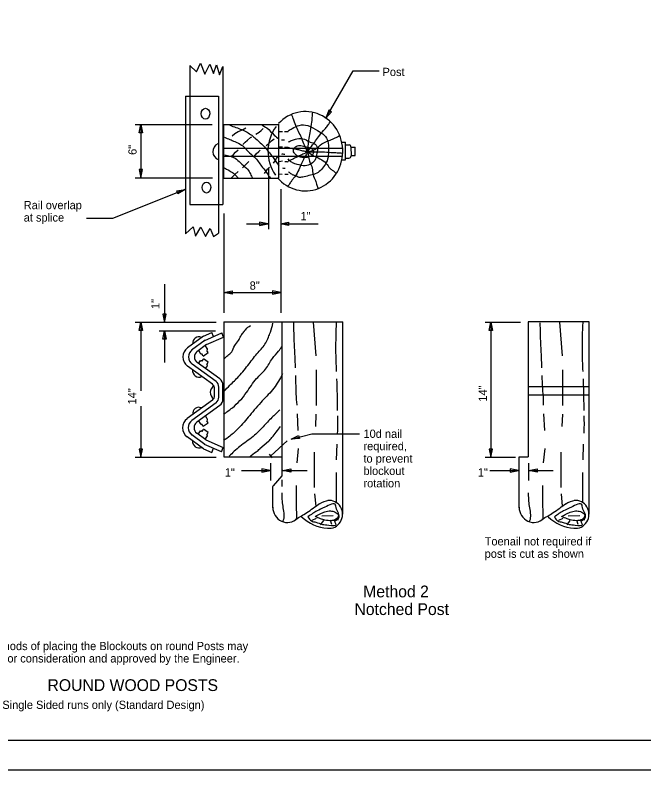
# Model space of a CAD drawing. Extents: x -0.7 to 89.2, y -3.6 to 22.
# Drawn here: x 8.19 to 18.88, y 0 to 12.81 of the extents above; entities that cross this region are included whole.
import ezdxf

# ---------------------------------------------------------------- set-up
doc = ezdxf.new("R2010")
doc.units = 0
for name, color, linetype in [('Default', 7, 'Continuous'), ('SH_Border', 7, 'Continuous'), ('ST_Text', 7, 'Continuous')]:
    doc.layers.add(name, color=color, linetype=linetype)

msp = doc.modelspace()

# ---------------------------------------------------------------- linework, layer by layer
at = {"layer": 'Default'}
for p, q in [((11.164, 11.957), (11.164, 11.443)), ((11.724, 11.937), (11.724, 9.599)), ((11.089, 11.438), (11.089, 9.101)), ((11.089, 11.438), (11.649, 11.438)), ((11.164, 11.438), (11.164, 9.599)), ((11.649, 11.438), (11.649, 9.111)), ((10.233, 10.953), (11.539, 10.953)), ((10.327, 10.953), (10.327, 10.375)), ((11.738, 10.955), (12.677, 10.955)), ((11.738, 10.046), (11.738, 10.955)), ((12.676, 10.046), (12.676, 10.956)), ((12.721, 10.693), (12.771, 10.694)), ((13.744, 10.653), (13.805, 10.653)), ((13.805, 10.353), (13.805, 10.653)), ((11.73, 10.555), (13.754, 10.555)), ((12.68, 10.573), (12.736, 10.577)), ((13.757, 10.559), (13.757, 10.559)), ((13.805, 10.611), (13.873, 10.611)), ((13.898, 10.576), (13.9, 10.423)), ((13.898, 10.57), (13.97, 10.57)), ((13.97, 10.43), (13.97, 10.57)), ((11.73, 10.417), (13.754, 10.417)), ((13.805, 10.386), (13.864, 10.386)), ((13.9, 10.43), (13.97, 10.43)), ((10.327, 10.375), (10.327, 10.049)), ((12.68, 10.328), (12.734, 10.336)), ((13.744, 10.353), (13.805, 10.353)), ((12.498, 10.211), (12.498, 9.176)), ((10.233, 10.049), (11.548, 10.049)), ((11.738, 10.046), (12.676, 10.046)), ((12.676, 10.115), (12.732, 10.109)), ((12.706, 9.86), (12.706, 8.186)), ((11.164, 9.599), (11.649, 9.599)), ((11.649, 9.599), (11.724, 9.599)), ((11.738, 9.443), (11.738, 8.186)), ((12.122, 9.271), (12.487, 9.271)), ((12.7, 9.271), (13.341, 9.271)), ((10.733, 8.247), (10.733, 7.593)), ((11.738, 8.186), (11.738, 7.76)), ((11.739, 8.103), (12.706, 8.103)), ((12.706, 8.186), (12.706, 7.76)), ((10.233, 7.601), (11.607, 7.601)), ((10.327, 7.601), (10.327, 6.434)), ((11.738, 7.605), (11.738, 5.315)), ((11.738, 7.605), (13.758, 7.605)), ((12.724, 7.605), (12.724, 4.993)), ((13.254, 7.599), (13.301, 7.027)), ((13.758, 4.338), (13.758, 7.605)), ((16.18, 7.601), (16.78, 7.601)), ((16.275, 7.601), (16.275, 6.434)), ((16.911, 7.605), (16.911, 5.315)), ((17.944, 7.605), (16.911, 7.605)), ((17.441, 7.599), (17.488, 7.027)), ((17.944, 4.338), (17.944, 7.605)), ((10.639, 7.45), (11.597, 7.45)), ((10.733, 7.45), (10.733, 6.915)), ((11.393, 7.363), (11.12, 7.163)), ((11.393, 7.364), (11.537, 7.426)), ((11.418, 7.291), (11.707, 7.417)), ((11.447, 7.22), (11.736, 7.346)), ((11.564, 7.356), (11.537, 7.426)), ((11.733, 7.347), (11.706, 7.416)), ((11.42, 7.292), (11.19, 7.124)), ((11.446, 7.22), (11.279, 7.098)), ((11.457, 7.153), (11.427, 7.2)), ((11.341, 7.07), (11.312, 7.116)), ((11.39, 7.024), (11.366, 7.06)), ((11.389, 7.024), (11.472, 7.083)), ((11.472, 7.083), (11.449, 7.118)), ((11.311, 6.898), (11.343, 6.948)), ((11.371, 6.938), (11.396, 6.977)), ((11.474, 6.919), (11.396, 6.977)), ((11.544, 6.546), (11.121, 6.855)), ((11.607, 6.591), (11.203, 6.886)), ((11.67, 6.636), (11.286, 6.917)), ((11.429, 6.812), (11.46, 6.86)), ((11.45, 6.881), (11.474, 6.918)), ((13.309, 6.793), (13.309, 6.188)), ((17.495, 6.793), (17.495, 6.188)), ((11.582, 6.355), (11.582, 6.469)), ((11.653, 6.325), (11.653, 6.499)), ((11.653, 6.407), (11.653, 6.418)), ((11.724, 6.296), (11.724, 6.528)), ((16.275, 6.434), (16.275, 6.176)), ((16.911, 6.506), (17.946, 6.509)), ((11.544, 6.278), (11.114, 5.962)), ((16.911, 6.365), (17.945, 6.369)), ((10.327, 6.176), (10.327, 5.306)), ((11.607, 6.233), (11.196, 5.932)), ((11.67, 6.188), (11.279, 5.901)), ((16.275, 6.176), (16.275, 5.306)), ((12.985, 6.046), (12.997, 5.759)), ((13.304, 6.039), (13.295, 5.829)), ((17.172, 6.046), (17.184, 5.759)), ((17.49, 6.039), (17.481, 5.829)), ((11.341, 5.878), (11.312, 5.923)), ((11.457, 5.96), (11.427, 6.008)), ((11.472, 5.89), (11.449, 5.926)), ((11.39, 5.831), (11.366, 5.868)), ((11.371, 5.745), (11.396, 5.784)), ((11.389, 5.832), (11.472, 5.89)), ((11.474, 5.726), (11.396, 5.784)), ((11.393, 5.45), (11.114, 5.654)), ((11.414, 5.526), (11.196, 5.685)), ((11.436, 5.601), (11.279, 5.716)), ((11.311, 5.705), (11.343, 5.755)), ((11.429, 5.619), (11.46, 5.668)), ((11.45, 5.688), (11.474, 5.725)), ((12.882, 5.612), (13.232, 5.704)), ((13.232, 5.704), (14.046, 5.704)), ((11.702, 5.4), (11.413, 5.526)), ((11.436, 5.601), (11.73, 5.473)), ((12.135, 5.58), (12.135, 5.58)), ((12.5, 5.575), (12.352, 5.447)), ((12.535, 5.33), (12.815, 5.584)), ((13.657, 5.528), (13.649, 5.263)), ((17.843, 5.528), (17.836, 5.263)), ((11.391, 5.451), (11.535, 5.388)), ((11.534, 5.388), (11.563, 5.461)), ((11.701, 5.4), (11.73, 5.474)), ((13.003, 5.454), (12.978, 5.212)), ((13.275, 5.392), (13.275, 4.794)), ((17.19, 5.454), (17.165, 5.212)), ((17.462, 5.392), (17.462, 4.794)), ((10.233, 5.306), (11.332, 5.306)), ((11.332, 5.306), (11.607, 5.306)), ((11.738, 5.315), (12.729, 5.315)), ((12.566, 5.296), (12.515, 5.357)), ((16.18, 5.306), (16.504, 5.306)), ((16.504, 5.306), (16.694, 5.306)), ((16.756, 4.524), (16.756, 5.315)), ((16.756, 5.315), (16.911, 5.315)), ((12.534, 5.207), (12.534, 4.911)), ((16.917, 5.207), (16.917, 4.911)), ((12.037, 5.08), (12.527, 5.08)), ((12.74, 5.08), (13.155, 5.08)), ((16.257, 5.08), (16.746, 5.08)), ((16.922, 5.08), (17.336, 5.08)), ((12.724, 4.993), (12.576, 4.823)), ((12.724, 4.922), (12.724, 4.808)), ((12.57, 4.524), (12.57, 4.811)), ((12.576, 4.816), (12.576, 4.823)), ((13.282, 4.688), (13.302, 4.474)), ((17.469, 4.688), (17.489, 4.474)), ((12.57, 4.446), (12.57, 4.524)), ((16.756, 4.446), (16.756, 4.524)), ((13.685, 4.325), (13.679, 4.359)), ((17.871, 4.325), (17.866, 4.359)), ((13.241, 4.239), (13.315, 4.275)), ((13.382, 4.161), (13.436, 4.232)), ((13.403, 4.31), (13.598, 4.318)), ((13.571, 4.168), (13.55, 4.239)), ((13.686, 4.246), (13.605, 4.239)), ((13.605, 4.239), (13.645, 4.239)), ((17.428, 4.239), (17.502, 4.275)), ((17.569, 4.161), (17.623, 4.232)), ((17.589, 4.31), (17.784, 4.318)), ((17.757, 4.168), (17.737, 4.239)), ((17.872, 4.246), (17.792, 4.239)), ((17.792, 4.239), (17.831, 4.239))]:
    msp.add_line(p, q, dxfattribs=at)
for points in [[(11.164, 11.957), (11.276, 11.848), (11.341, 11.997), (11.416, 11.809), (11.5, 11.977), (11.565, 11.819), (11.612, 11.967), (11.668, 11.799), (11.724, 11.937)], [(13.471, 11.065), (13.936, 11.864), (14.376, 11.864)], [(11.878, 10.765), (11.924, 10.803), (11.984, 10.834), (12.057, 10.867), (12.11, 10.896)], [(12.285, 10.788), (12.339, 10.827), (12.373, 10.852), (12.41, 10.885)], [(12.062, 10.617), (12.103, 10.653), (12.141, 10.69), (12.193, 10.732), (12.214, 10.743)], [(12.46, 10.597), (12.504, 10.633), (12.548, 10.675), (12.594, 10.712)], [(11.876, 10.423), (11.903, 10.447), (11.94, 10.487), (11.984, 10.527)], [(12.258, 10.416), (12.289, 10.456), (12.331, 10.498), (12.356, 10.518)], [(12.582, 10.301), (12.609, 10.336), (12.632, 10.376), (12.659, 10.414)], [(12.057, 10.219), (12.099, 10.266), (12.164, 10.325)], [(11.865, 10.042), (11.928, 10.104), (11.984, 10.157)], [(12.429, 10.122), (12.458, 10.16), (12.483, 10.197), (12.515, 10.233)], [(11.081, 9.852), (9.847, 9.362), (9.408, 9.362)], [(11.089, 9.101), (11.22, 9.22), (11.257, 9.062), (11.351, 9.21), (11.426, 9.052), (11.509, 9.19), (11.565, 9.052), (11.649, 9.111)]]:
    msp.add_lwpolyline(points, dxfattribs=at)
for points in [[(13.521, 11.198), (13.471, 11.065), (13.568, 11.169)], [(10.299, 10.813), (10.327, 10.953), (10.355, 10.813)], [(10.299, 10.189), (10.327, 10.049), (10.355, 10.189)], [(10.94, 9.828), (11.081, 9.852), (10.96, 9.776)], [(12.347, 9.243), (12.487, 9.271), (12.347, 9.299)], [(12.84, 9.243), (12.7, 9.271), (12.84, 9.299)], [(11.879, 8.075), (11.739, 8.103), (11.879, 8.131)], [(12.566, 8.075), (12.706, 8.103), (12.566, 8.131)], [(10.705, 7.733), (10.733, 7.593), (10.761, 7.733)], [(10.299, 7.461), (10.327, 7.601), (10.355, 7.461)], [(16.247, 7.461), (16.275, 7.601), (16.303, 7.461)], [(10.705, 7.31), (10.733, 7.45), (10.761, 7.31)], [(13.024, 5.623), (12.882, 5.612), (13.008, 5.677)], [(10.299, 5.446), (10.327, 5.306), (10.355, 5.446)], [(16.247, 5.446), (16.275, 5.306), (16.303, 5.446)], [(12.387, 5.052), (12.527, 5.08), (12.387, 5.108)], [(12.88, 5.052), (12.74, 5.08), (12.88, 5.108)], [(16.606, 5.052), (16.746, 5.08), (16.606, 5.108)], [(17.062, 5.052), (16.922, 5.08), (17.062, 5.108)]]:
    msp.add_lwpolyline(points, close=True, dxfattribs=at)
for centre in [(11.426, 11.137), (11.443, 9.885)]:
    msp.add_ellipse(centre, major_axis=(0.0005, 0.0936), ratio=0.773782, dxfattribs=at)
for centre, major_axis, start_param, end_param in [((13.124, 10.501), (0, 0.673), 2.303639, 7.079119), ((13.124, 10.501), (0, 0.673), 0.900881, 2.214399), ((11.684, 10.495), (0, -0.141), 3.514867, 5.984065), ((13.87, 10.58), (0, 0.03), 4.574534, 6.237266), ((13.871, 10.581), (0, -0.0298), 1.431351, 1.439211), ((13.869, 10.418), (0, -0.0326), 6.093782, 8.002272), ((11.313, 7.244), (0, -0.107), 2.687211, 4.851441), ((11.221, 7.009), (0, -0.187), 3.747084, 5.680264), ((11.283, 7.009), (0, -0.15), 3.747137, 5.680324), ((11.346, 7.009), (0, -0.112), 3.747102, 5.680297), ((11.354, 7.081), (0, -0.0195), 5.247458, 6.879592), ((11.441, 7.141), (0, 0.0198), 3.70437, 5.352473), ((11.355, 6.925), (0, 0.021), 5.452301, 7.118326), ((11.441, 6.862), (0, 0.021), 4.196406, 5.73538), ((11.316, 6.782), (0, -0.115), 4.640651, 6.714317), ((11.494, 6.469), (0, 0.0937), 4.712389, 5.680377), ((11.547, 6.499), (0, 0.112), 4.712389, 5.68034), ((11.6, 6.528), (0, 0.131), 4.712389, 5.680267), ((11.622, 6.406), (0, -0.12), 3.613765, 5.74142), ((11.494, 6.355), (0, -0.0937), 0.605563, 1.570796), ((11.547, 6.325), (0, -0.112), 0.605651, 1.570796), ((11.6, 6.296), (0, -0.131), 0.605566, 1.570796), ((11.31, 6.048), (0, -0.107), 2.687211, 4.851441), ((11.214, 5.808), (0, -0.187), 3.747091, 5.68028), ((11.277, 5.808), (0, -0.15), 3.747115, 5.680355), ((11.339, 5.808), (0, -0.112), 3.747102, 5.680258), ((11.441, 5.948), (0, 0.0198), 3.70437, 5.352473), ((11.354, 5.888), (0, -0.0195), 5.247458, 6.879592), ((11.355, 5.732), (0, 0.021), 5.452301, 7.118326), ((11.441, 5.669), (0, 0.021), 4.196406, 5.73538), ((11.316, 5.579), (0, -0.115), 4.640651, 6.714317), ((13.603, 4.072), (0, 0.508), 0.179437, 0.530353), ((13.531, 4.338), (0, 0.237), 2.997307, 6.40595), ((17.789, 4.072), (0, 0.508), 0.179437, 0.530353), ((17.718, 4.338), (0, 0.237), 2.997307, 6.40595), ((12.819, 4.464), (0, -0.264), 4.726587, 7.018323), ((17.005, 4.464), (0, -0.264), 4.726587, 7.018323), ((13.545, 4.883), (0, -0.78), 5.564047, 6.222034), ((17.732, 4.883), (0, -0.78), 5.564047, 6.222034)]:
    msp.add_ellipse(centre, major_axis=major_axis, ratio=0.944544, start_param=start_param, end_param=end_param, dxfattribs=at)
for points in [[(13.162, 10.5), (13.172, 10.591), (13.189, 10.721), (13.21, 10.845), (13.235, 10.997), (13.243, 11.097), (13.25, 11.161)], [(13.16, 10.496), (13.122, 10.575), (13.078, 10.681), (13.033, 10.785), (12.985, 10.885), (12.941, 10.993), (12.928, 11.031), (12.891, 11.126)], [(11.842, 10.942), (11.945, 10.905), (12.135, 10.823), (12.285, 10.712), (12.429, 10.573), (12.563, 10.409), (12.659, 10.279), (12.679, 10.254)], [(12.373, 10.956), (12.467, 10.896), (12.596, 10.776), (12.676, 10.704)], [(12.834, 10.849), (12.901, 10.887), (13.02, 10.94), (13.164, 10.938), (13.329, 10.852), (13.448, 10.77), (13.505, 10.673), (13.517, 10.533), (13.509, 10.398), (13.465, 10.281), (13.398, 10.191), (13.317, 10.129), (13.212, 10.093), (13.102, 10.067), (13.02, 10.058), (12.955, 10.084), (12.905, 10.102), (12.855, 10.14), (12.836, 10.153)], [(13.164, 10.498), (13.212, 10.558), (13.283, 10.657), (13.348, 10.746), (13.433, 10.852), (13.477, 10.902), (13.525, 10.962), (13.548, 11)], [(12.68, 10.838), (12.73, 10.838), (12.736, 10.838)], [(12.767, 10.837), (12.807, 10.836), (12.832, 10.838)], [(13.166, 10.496), (13.285, 10.533), (13.404, 10.626), (13.546, 10.69), (13.628, 10.726), (13.707, 10.768)], [(11.749, 10.737), (11.928, 10.664), (12.041, 10.606), (12.176, 10.476), (12.277, 10.383), (12.396, 10.226), (12.479, 10.12), (12.527, 10.051), (12.536, 10.045)], [(12.836, 10.661), (12.903, 10.69), (12.978, 10.71), (13.112, 10.704), (13.208, 10.655), (13.292, 10.622), (13.329, 10.529), (13.319, 10.465), (13.298, 10.37), (13.225, 10.288), (13.12, 10.253), (12.987, 10.277), (12.905, 10.306), (12.857, 10.343), (12.834, 10.37)], [(12.767, 10.574), (12.795, 10.571), (12.834, 10.571)], [(13.16, 10.493), (13.083, 10.505), (13.012, 10.522), (12.92, 10.54), (12.861, 10.553), (12.84, 10.56)], [(12.92, 10.493), (12.934, 10.551), (12.968, 10.584), (13.047, 10.597), (13.143, 10.577), (13.239, 10.542), (13.26, 10.482), (13.208, 10.412), (13.137, 10.394), (13.051, 10.398), (12.987, 10.425), (12.943, 10.46), (12.924, 10.493)], [(11.754, 10.439), (11.932, 10.381), (12.018, 10.308), (12.124, 10.213), (12.183, 10.135), (12.218, 10.058), (12.229, 10.042)], [(12.727, 10.454), (12.744, 10.456), (12.774, 10.449)], [(13.166, 10.493), (13.12, 10.414), (13.093, 10.363), (13.045, 10.266), (13.024, 10.213), (12.966, 10.1), (12.945, 10.069), (12.924, 10.045), (12.895, 10.003), (12.866, 9.965), (12.847, 9.934), (12.834, 9.914), (12.828, 9.91)], [(13.16, 10.496), (13.116, 10.465), (13.049, 10.434), (12.941, 10.381), (12.863, 10.345), (12.834, 10.334)], [(13.16, 10.493), (13.275, 10.42), (13.404, 10.356), (13.494, 10.277), (13.559, 10.195), (13.601, 10.169), (13.638, 10.135), (13.655, 10.127)], [(13.164, 10.493), (13.333, 10.491), (13.49, 10.487), (13.619, 10.478), (13.705, 10.474), (13.755, 10.469)], [(13.164, 10.493), (13.179, 10.398), (13.202, 10.314), (13.239, 10.215), (13.256, 10.1), (13.298, 10.005), (13.321, 9.923), (13.342, 9.866)], [(12.775, 10.328), (12.776, 10.328), (12.826, 10.325), (12.832, 10.328)], [(11.752, 10.217), (11.888, 10.138), (11.938, 10.096), (11.974, 10.045)], [(12.738, 10.218), (12.763, 10.213), (12.78, 10.214)], [(12.776, 10.113), (12.815, 10.109), (12.83, 10.111)], [(11.743, 6.428), (11.841, 6.528), (11.993, 6.682), (12.168, 6.893), (12.32, 7.086), (12.451, 7.247), (12.495, 7.343), (12.531, 7.432), (12.574, 7.584)], [(12.922, 7.587), (12.932, 7.234), (12.946, 6.95), (12.95, 6.822)], [(13.649, 7.595), (13.638, 7.127), (13.65, 6.765)], [(17.108, 7.587), (17.119, 7.234), (17.132, 6.95), (17.137, 6.822)], [(17.836, 7.595), (17.824, 7.127), (17.837, 6.765)], [(11.739, 6.974), (11.808, 7.036), (11.874, 7.097), (11.924, 7.201), (11.986, 7.286), (12.026, 7.363), (12.066, 7.42), (12.11, 7.478), (12.193, 7.544)], [(11.732, 6.036), (11.884, 6.147), (12.124, 6.405), (12.295, 6.643), (12.448, 6.801), (12.564, 6.982), (12.669, 7.109), (12.725, 7.183)], [(12.735, 6.72), (12.588, 6.478), (12.393, 6.265), (12.178, 6.016), (11.983, 5.795), (11.842, 5.667), (11.734, 5.589)], [(12.955, 6.694), (12.959, 6.566), (12.979, 6.196), (12.98, 6.189)], [(17.141, 6.694), (17.146, 6.566), (17.166, 6.196), (17.166, 6.189)], [(13.655, 6.637), (13.658, 6.544), (13.667, 6.103)], [(17.841, 6.637), (17.845, 6.544), (17.853, 6.103)], [(12.688, 6.108), (12.554, 5.98), (12.406, 5.824), (12.238, 5.66), (12.01, 5.489), (11.828, 5.324)], [(13.668, 6.011), (13.671, 5.854), (13.667, 5.717)], [(17.855, 6.011), (17.858, 5.854), (17.853, 5.717)], [(12.5, 5.575), (12.557, 5.643), (12.703, 5.828)], [(12.179, 5.316), (12.288, 5.401), (12.352, 5.447)], [(13.645, 5.049), (13.645, 4.836), (13.645, 4.587), (13.645, 4.544)], [(17.832, 5.049), (17.832, 4.836), (17.832, 4.587), (17.832, 4.544)], [(12.966, 4.83), (12.966, 4.659), (12.973, 4.275)], [(17.152, 4.83), (17.152, 4.659), (17.159, 4.275)], [(12.724, 4.702), (12.724, 4.68), (12.744, 4.446), (12.744, 4.225), (12.737, 4.211)], [(16.911, 4.702), (16.911, 4.68), (16.931, 4.446), (16.931, 4.225), (16.924, 4.211)], [(12.959, 4.254), (13.147, 4.367), (13.366, 4.524)], [(13.168, 4.296), (13.322, 4.396), (13.456, 4.46), (13.638, 4.495), (13.645, 4.452), (13.686, 4.359), (13.686, 4.267), (13.625, 4.21), (13.645, 4.168), (13.524, 4.154), (13.416, 4.168), (13.302, 4.204), (13.228, 4.225), (13.168, 4.296)], [(17.146, 4.254), (17.334, 4.367), (17.552, 4.524)], [(17.354, 4.296), (17.509, 4.396), (17.643, 4.46), (17.824, 4.495), (17.832, 4.452), (17.872, 4.359), (17.872, 4.267), (17.812, 4.21), (17.831, 4.168), (17.71, 4.154), (17.603, 4.168), (17.489, 4.204), (17.415, 4.225), (17.354, 4.296)], [(13.288, 4.303), (13.376, 4.346), (13.456, 4.382), (13.55, 4.396), (13.631, 4.375), (13.685, 4.325), (13.658, 4.268), (13.571, 4.232), (13.456, 4.239), (13.382, 4.261), (13.295, 4.303)], [(17.475, 4.303), (17.562, 4.346), (17.643, 4.382), (17.737, 4.396), (17.818, 4.375), (17.871, 4.325), (17.845, 4.268), (17.757, 4.232), (17.643, 4.239), (17.569, 4.261), (17.482, 4.303)]]:
    msp.add_spline(points, degree=3, dxfattribs=at)
at = {"layer": 'SH_Border'}
msp.add_lwpolyline([(1.5, 21.5), (33.5, 21.5), (33.5, 0.5), (1.5, 0.5)], close=True, dxfattribs=at)
at = {"layer": 'ST_Text'}
msp.add_lwpolyline([(0, 0), (34, 0), (34, 22), (0, 22)], close=True, dxfattribs=at)

# ---------------------------------------------------------------- texts
at = {"layer": 'Default'}
for s, height, p in [('Post', 0.14, (14.435, 11.777)), ('Rail overlap', 0.14, (8.339, 9.517)), ('at splice', 0.14, (8.339, 9.307)), ('1"', 0.14, (13.042, 9.33)), ('8" ', 0.14, (12.178, 8.151)), ('10d nail ', 0.14, (14.111, 5.636)), ('required, ', 0.14, (14.111, 5.426)), ('to prevent ', 0.14, (14.111, 5.216)), ('blockout ', 0.14, (14.111, 5.006)), ('1"', 0.14, (11.755, 4.98)), ('1" ', 0.14, (16.054, 4.98)), ('rotation', 0.14, (14.111, 4.796)), ('Toenail not required if', 0.14, (16.17, 3.81)), ('post is cut as shown', 0.14, (16.17, 3.6)), ('  Method 2', 0.2, (13.958, 2.929)), ('Notched Post', 0.2, (13.958, 2.629)), ('Alternate methods of placing the Blockouts on round Posts may', 0.14, (6.886, 2.033)), ('be submitted for consideration and approved by the Engineer.', 0.14, (6.886, 1.823)), ('ROUND WOOD POSTS', 0.2, (8.743, 1.339)), ('Single Sided runs only (Standard Design)', 0.14, (7.976, 1.035))]:
    msp.add_text(s, height=height, dxfattribs=at).set_placement(p)
for s, p in [('6" ', (10.257, 10.439)), ('1" ', (10.646, 7.823)), ('14" ', (10.25, 6.203)), ('14" ', (16.208, 6.251))]:
    msp.add_text(s, height=0.14, rotation=90, dxfattribs=at).set_placement(p)

doc.saveas('drawing.dxf')
